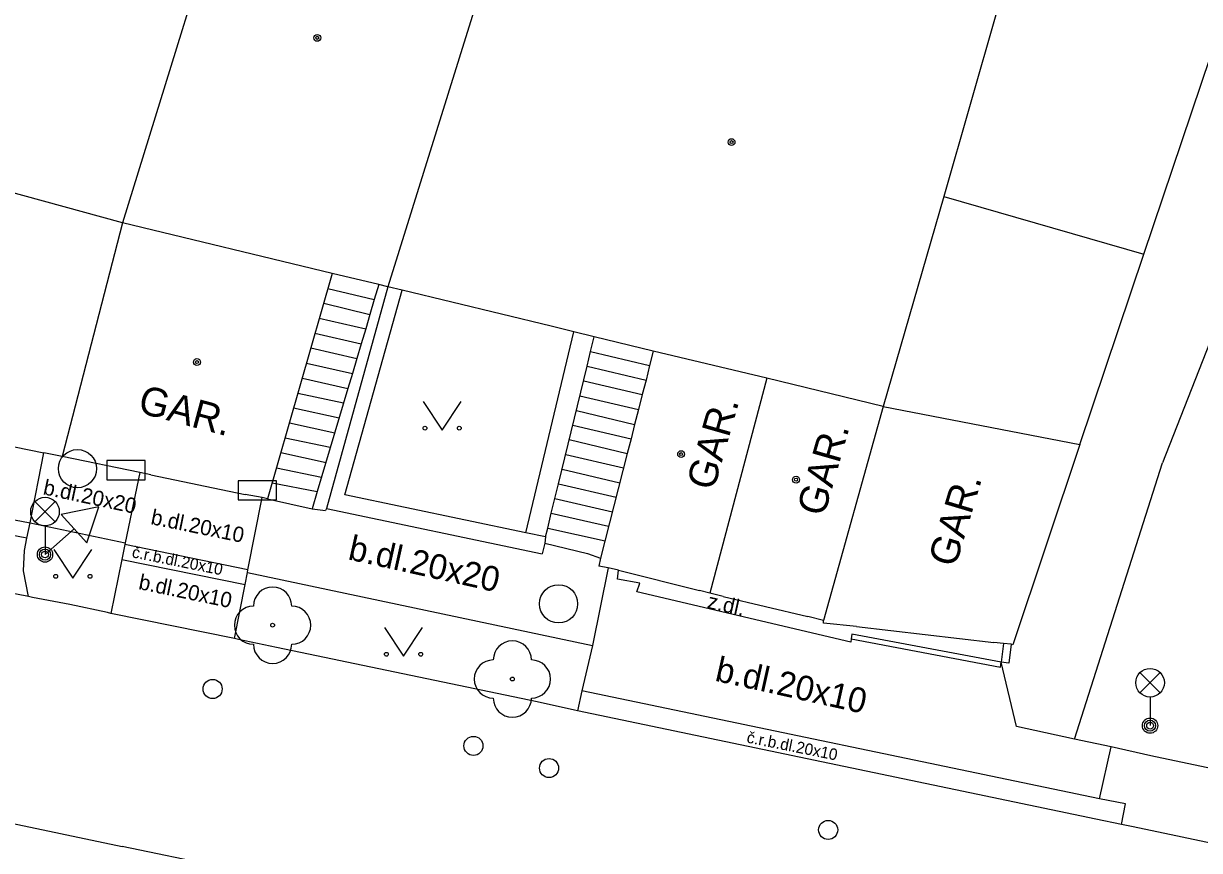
# Model space of a CAD drawing. Extents: x -595546 to -593986, y -1160845 to -1159202.
# Drawn here: x -594736.96 to -594706.17, y -1160781.24 to -1160759.59 of the extents above; entities that cross this region are included whole.
import ezdxf

# ---------------------------------------------------------------- set-up
doc = ezdxf.new("R2010")
doc.units = 0
for name, color, linetype in [('kanalizace - povrch.  znaky - skut. velikost', 7, 'Continuous'), ('Level 22', 7, 'Continuous'), ('Level 24', 7, 'Continuous'), ('Level 27', 7, 'Continuous'), ('Level 28', 7, 'Continuous'), ('Level 33', 7, 'Continuous'), ('Level 34', 7, 'Continuous'), ('Level 36', 7, 'Continuous'), ('Level 39', 7, 'Continuous'), ('Specificka linie pasportu komunikaci', 7, 'Continuous'), ('TM - budovy zdene_ betonove - VP', 7, 'Continuous'), ('TM - chodniky - VP', 7, 'Continuous'), ('TM - komunikace - VP', 7, 'Continuous'), ('TM - letecke snimky - pomocna linie', 7, 'Continuous'), ('TM - plot drateny_ kovovy - VP', 7, 'Continuous'), ('TM - podezdivka plotu - VP', 7, 'Continuous'), ('TM - pomocna konstrukcni linie', 7, 'Continuous'), ('TM - popis objektu', 7, 'Continuous'), ('TM - popis povrchu', 7, 'Continuous'), ('TM - rozhrani mezi zpev. plochami mezi sebou - VP', 7, 'Continuous'), ('TM - rozhrani ploch obecne - VP', 7, 'Continuous'), ('TM - schody - VP', 7, 'Continuous'), ('TM - vjezd na pozemek', 7, 'Continuous'), ('TM - vstup do budovy - zdene_ betonove', 7, 'Continuous'), ('TM - zed operna - VP', 7, 'Continuous')]:
    doc.layers.add(name, color=color, linetype=linetype)

msp = doc.modelspace()

# ---------------------------------------------------------------- linework, layer by layer
at = {"layer": 'kanalizace - povrch.  znaky - skut. velikost'}
for points in [[(-594715.27, -1160775.57), (-594715.29, -1160775.7)], [(-594715.29, -1160775.7), (-594711.38, -1160776.44)], [(-594711.36, -1160776.31), (-594715.27, -1160775.57)], [(-594711.38, -1160776.44), (-594711.36, -1160776.31)]]:
    msp.add_lwpolyline(points, dxfattribs=at)
at = {"layer": 'Level 22'}
for centre in [(-594730.44, -1160775.34), (-594724.16, -1160776.75)]:
    msp.add_circle(centre, 0.05, dxfattribs=at)
for centre, start, end in [((-594730.44, -1160774.84), 0, 180), ((-594730.94, -1160775.34), 90, 270), ((-594729.94, -1160775.34), 270, 90), ((-594730.44, -1160775.84), 180, 0), ((-594724.16, -1160776.25), 0, 180), ((-594724.66, -1160776.75), 90, 270), ((-594723.66, -1160776.75), 270, 90), ((-594724.16, -1160777.25), 180, 0)]:
    msp.add_arc(centre, 0.5, start, end, dxfattribs=at)
at = {"layer": 'Level 24'}
for points in [[(-594734.778, -1160771.529), (-594733.778, -1160771.529), (-594733.778, -1160771.029), (-594734.778, -1160771.029)], [(-594731.337, -1160772.058), (-594730.337, -1160772.058), (-594730.337, -1160771.558), (-594731.337, -1160771.558)]]:
    msp.add_lwpolyline(points, close=True, dxfattribs=at)
at = {"layer": 'Level 27'}
for centre in [(-594735.55, -1160771.24), (-594722.95, -1160774.78)]:
    msp.add_circle(centre, 0.5, dxfattribs=at)
at = {"layer": 'Level 28'}
for centre in [(-594732.01, -1160777.01), (-594725.18, -1160778.5), (-594723.2, -1160779.08), (-594715.89, -1160780.7)]:
    msp.add_circle(centre, 0.25, dxfattribs=at)
at = {"layer": 'Level 33'}
for p, q in [((-594736.665, -1160772.63), (-594736.135, -1160772.1)), ((-594736.665, -1160772.1), (-594736.135, -1160772.63)), ((-594736.4, -1160772.74), (-594736.4, -1160773.49)), ((-594707.725, -1160777.11), (-594707.195, -1160776.58)), ((-594707.725, -1160776.58), (-594707.195, -1160777.11)), ((-594707.46, -1160777.22), (-594707.46, -1160777.97))]:
    msp.add_line(p, q, dxfattribs=at)
for centre, radius in [((-594736.4, -1160772.365), 0.375), ((-594736.4, -1160773.49), 0.2), ((-594736.4, -1160773.49), 0.145), ((-594736.4, -1160773.49), 0.0876), ((-594707.46, -1160776.845), 0.375), ((-594707.46, -1160777.97), 0.2), ((-594707.46, -1160777.97), 0.145), ((-594707.46, -1160777.97), 0.0876)]:
    msp.add_circle(centre, radius, dxfattribs=at)
at = {"layer": 'Level 34'}
msp.add_line((-594735.64, -1160772.813), (-594736.4, -1160773.49), dxfattribs=at)
msp.add_lwpolyline([(-594735.973, -1160772.439), (-594735.307, -1160773.186), (-594734.994, -1160772.236)], close=True, dxfattribs=at)
at = {"layer": 'Level 36'}
for points in [[(-594726.5, -1160769.48), (-594726, -1160770.23), (-594725.5, -1160769.48)], [(-594736.17, -1160773.36), (-594735.67, -1160774.11), (-594735.17, -1160773.36)], [(-594727.51, -1160775.4), (-594727.01, -1160776.15), (-594726.51, -1160775.4)]]:
    msp.add_lwpolyline(points, dxfattribs=at)
for centre in [(-594726.45, -1160770.18), (-594725.551, -1160770.18), (-594736.12, -1160774.06), (-594735.221, -1160774.06), (-594727.46, -1160776.1), (-594726.561, -1160776.1)]:
    msp.add_circle(centre, 0.05, dxfattribs=at)
at = {"layer": 'Level 39'}
for centre, radius in [((-594729.27, -1160759.96), 0.09), ((-594729.27, -1160759.96), 0.0398), ((-594718.42, -1160762.69), 0.09), ((-594718.42, -1160762.69), 0.0398), ((-594732.42, -1160768.45), 0.09), ((-594732.42, -1160768.45), 0.0398), ((-594719.74, -1160770.86), 0.09), ((-594719.74, -1160770.86), 0.0398), ((-594716.73, -1160771.53), 0.09), ((-594716.73, -1160771.53), 0.0398)]:
    msp.add_circle(centre, radius, dxfattribs=at)
at = {"layer": 'Specificka linie pasportu komunikaci'}
msp.add_lwpolyline([(-594709.44, -1160778.32), (-594707.13, -1160771.09)], dxfattribs=at)
at = {"layer": 'TM - budovy zdene_ betonove - VP'}
for points in [[(-594731.13, -1160754.32), (-594734.37, -1160764.8)], [(-594724.28, -1160756.4), (-594727.42, -1160766.48)], [(-594711.48, -1160759.3), (-594712.86, -1160764.11)], [(-594734.37, -1160764.8), (-594738.52, -1160763.67)], [(-594712.86, -1160764.11), (-594714.45, -1160769.61)], [(-594734.37, -1160764.8), (-594735.95, -1160770.92)], [(-594728.88, -1160766.13), (-594734.37, -1160764.8)], [(-594728.88, -1160766.13), (-594730.57, -1160772.03)], [(-594727.66, -1160766.42), (-594728.88, -1160766.13)], [(-594727.42, -1160766.48), (-594727.66, -1160766.42)], [(-594727.05, -1160766.57), (-594727.42, -1160766.48)], [(-594723.14, -1160767.51), (-594727.05, -1160766.57)], [(-594722.55, -1160767.66), (-594723.14, -1160767.51)], [(-594722.02, -1160767.79), (-594722.55, -1160767.66)], [(-594720.47, -1160768.16), (-594722.02, -1160767.79)], [(-594720.47, -1160768.16), (-594720.57, -1160768.54), (-594720.66, -1160768.92), (-594720.76, -1160769.3), (-594720.86, -1160769.69), (-594720.96, -1160770.08), (-594721.05, -1160770.46), (-594721.15, -1160770.84), (-594721.85, -1160773.58)], [(-594717.5, -1160768.87), (-594720.47, -1160768.16)], [(-594717.5, -1160768.87), (-594718.99, -1160774.5)], [(-594714.45, -1160769.61), (-594717.5, -1160768.87)], [(-594714.45, -1160769.61), (-594716.01, -1160775.22)], [(-594714.45, -1160769.61), (-594709.3, -1160770.61)], [(-594709.3, -1160770.61), (-594711.05, -1160775.85)], [(-594735.95, -1160770.92), (-594736.43, -1160770.83)], [(-594733.92, -1160771.34), (-594735.95, -1160770.92)], [(-594733.63, -1160771.4), (-594733.92, -1160771.34)], [(-594730.71, -1160772), (-594731.16, -1160771.92)], [(-594730.57, -1160772.03), (-594730.71, -1160772)], [(-594721.85, -1160773.58), (-594721.9, -1160773.79)], [(-594721.65, -1160773.84), (-594721.9, -1160773.79)], [(-594721.38, -1160773.9), (-594721.65, -1160773.84)], [(-594718.99, -1160774.5), (-594719.26, -1160774.43)], [(-594718.64, -1160774.59), (-594718.99, -1160774.5)], [(-594716.01, -1160775.22), (-594716.42, -1160775.11)], [(-594716.01, -1160775.29), (-594716.01, -1160775.22)], [(-594715.15, -1160775.37), (-594716.01, -1160775.29)], [(-594711.3, -1160775.82), (-594711.55, -1160775.79)], [(-594711.1, -1160775.84), (-594711.3, -1160775.82)], [(-594711.05, -1160775.85), (-594711.1, -1160775.84)]]:
    msp.add_lwpolyline(points, dxfattribs=at)
at = {"layer": 'TM - chodniky - VP'}
for points in [[(-594736.88, -1160773.06), (-594736.79, -1160772.66)], [(-594736.79, -1160772.66), (-594734.3, -1160773.18)], [(-594736.94, -1160773.38), (-594736.88, -1160773.06)], [(-594736.96, -1160773.92), (-594736.94, -1160773.38)], [(-594734.31, -1160773.23), (-594734.39, -1160773.62)], [(-594734.3, -1160773.18), (-594734.31, -1160773.23)], [(-594734.39, -1160773.62), (-594734.68, -1160775.03)], [(-594736.83, -1160774.59), (-594736.96, -1160773.92)], [(-594731.16, -1160774.27), (-594731.1, -1160773.96)], [(-594731.1, -1160773.96), (-594731.09, -1160773.89)], [(-594731.1, -1160773.96), (-594722.06, -1160775.87)], [(-594731.44, -1160775.69), (-594731.16, -1160774.27)], [(-594722.06, -1160775.87), (-594722.34, -1160777.06)], [(-594710.96, -1160777.99), (-594711.36, -1160776.31)], [(-594722.34, -1160777.06), (-594722.45, -1160777.58)], [(-594709.44, -1160778.32), (-594710.96, -1160777.99)], [(-594708.48, -1160778.52), (-594709.44, -1160778.32)], [(-594707.44, -1160778.76), (-594708.48, -1160778.52)], [(-594697.12, -1160780.93), (-594707.44, -1160778.76)]]:
    msp.add_lwpolyline(points, dxfattribs=at)
at = {"layer": 'TM - komunikace - VP'}
for points in [[(-594736.83, -1160774.59), (-594742.64, -1160773.46)], [(-594736.73, -1160774.61), (-594736.83, -1160774.59)], [(-594735.75, -1160774.8), (-594736.73, -1160774.61)], [(-594734.76, -1160775.01), (-594735.75, -1160774.8)], [(-594734.68, -1160775.03), (-594734.76, -1160775.01)], [(-594731.44, -1160775.69), (-594734.68, -1160775.03)], [(-594731.33, -1160775.71), (-594731.44, -1160775.69)], [(-594730.34, -1160775.92), (-594731.33, -1160775.71)], [(-594723.51, -1160777.35), (-594730.34, -1160775.92)], [(-594722.53, -1160777.56), (-594723.51, -1160777.35)], [(-594722.45, -1160777.58), (-594722.53, -1160777.56)], [(-594708.88, -1160780.42), (-594722.45, -1160777.58)], [(-594739.23, -1160780.11), (-594734.38, -1160781.13)], [(-594708.21, -1160780.56), (-594708.88, -1160780.42)], [(-594707.9, -1160780.62), (-594708.21, -1160780.56)], [(-594697.47, -1160782.82), (-594707.9, -1160780.62)], [(-594729.33, -1160782.18), (-594734.38, -1160781.13)]]:
    msp.add_lwpolyline(points, dxfattribs=at)
at = {"layer": 'TM - letecke snimky - pomocna linie'}
for points in [[(-594707.62, -1160765.62), (-594703.12, -1160752.26)], [(-594700.06, -1160753.08), (-594707.13, -1160771.09)], [(-594712.86, -1160764.11), (-594707.62, -1160765.62)], [(-594709.3, -1160770.61), (-594707.62, -1160765.62)]]:
    msp.add_lwpolyline(points, dxfattribs=at)
at = {"layer": 'TM - plot drateny_ kovovy - VP'}
msp.add_lwpolyline([(-594722.19, -1160773.46), (-594721.85, -1160773.58)], dxfattribs=at)
at = {"layer": 'TM - podezdivka plotu - VP'}
for points in [[(-594727.66, -1160766.42), (-594727.78, -1160766.81), (-594727.89, -1160767.2), (-594728, -1160767.58), (-594728.12, -1160767.97), (-594728.23, -1160768.36), (-594728.35, -1160768.75), (-594728.47, -1160769.14), (-594729.27, -1160771.84), (-594729.4, -1160772.29)], [(-594727.42, -1160766.48), (-594729.03, -1160772.28)], [(-594729.4, -1160772.29), (-594729.05, -1160772.34)], [(-594729.03, -1160772.28), (-594729.05, -1160772.34)], [(-594729.03, -1160772.28), (-594723.38, -1160773.47)], [(-594723.29, -1160773.03), (-594723.31, -1160773.19)], [(-594723.31, -1160773.19), (-594723.38, -1160773.47)], [(-594711.3, -1160775.82), (-594711.36, -1160776.31)], [(-594711.16, -1160776.33), (-594711.36, -1160776.31)]]:
    msp.add_lwpolyline(points, dxfattribs=at)
at = {"layer": 'TM - pomocna konstrukcni linie'}
msp.add_lwpolyline([(-594723.29, -1160773.03), (-594723.23, -1160772.8), (-594723.14, -1160772.41), (-594723.05, -1160772.02), (-594722.95, -1160771.64), (-594722.2, -1160768.56), (-594722.11, -1160768.17), (-594722.02, -1160767.79)], dxfattribs=at)
at = {"layer": 'TM - rozhrani mezi zpev. plochami mezi sebou - VP'}
for points in [[(-594736.79, -1160772.66), (-594736.43, -1160770.83)], [(-594733.92, -1160771.34), (-594734.3, -1160773.18)], [(-594742.27, -1160771.61), (-594736.79, -1160772.66)], [(-594736.88, -1160773.06), (-594742.35, -1160772.01)], [(-594731.09, -1160773.89), (-594730.71, -1160772)], [(-594731.09, -1160773.89), (-594734.31, -1160773.23)], [(-594734.39, -1160773.62), (-594731.16, -1160774.27)], [(-594721.65, -1160773.84), (-594722.06, -1160775.87)], [(-594721.41, -1160774.13), (-594721.38, -1160773.9)], [(-594720.82, -1160774.24), (-594721.41, -1160774.13)], [(-594720.9, -1160774.47), (-594720.82, -1160774.24)], [(-594715.3, -1160775.78), (-594720.9, -1160774.47)], [(-594715.29, -1160775.7), (-594715.3, -1160775.78)], [(-594708.78, -1160779.89), (-594722.34, -1160777.06)], [(-594708.78, -1160779.89), (-594708.48, -1160778.52)], [(-594708.1, -1160780.02), (-594708.78, -1160779.89)], [(-594708.21, -1160780.56), (-594708.1, -1160780.02)]]:
    msp.add_lwpolyline(points, dxfattribs=at)
at = {"layer": 'TM - rozhrani ploch obecne - VP'}
msp.add_lwpolyline([(-594723.81, -1160772.92), (-594722.55, -1160767.66)], dxfattribs=at)
at = {"layer": 'TM - schody - VP'}
for points in [[(-594728.99, -1160766.52), (-594727.78, -1160766.81)], [(-594729.1, -1160766.91), (-594727.89, -1160767.2)], [(-594729.22, -1160767.3), (-594728, -1160767.58)], [(-594729.33, -1160767.69), (-594728.12, -1160767.97)], [(-594729.44, -1160768.08), (-594728.23, -1160768.36)], [(-594722.11, -1160768.17), (-594720.57, -1160768.54)], [(-594729.55, -1160768.48), (-594728.35, -1160768.75)], [(-594722.2, -1160768.56), (-594720.66, -1160768.92)], [(-594729.66, -1160768.87), (-594728.47, -1160769.14)], [(-594722.29, -1160768.94), (-594720.76, -1160769.3)], [(-594729.78, -1160769.26), (-594728.58, -1160769.52)], [(-594722.39, -1160769.33), (-594720.86, -1160769.69)], [(-594729.89, -1160769.65), (-594728.7, -1160769.91)], [(-594722.48, -1160769.72), (-594720.96, -1160770.08)], [(-594730, -1160770.04), (-594728.81, -1160770.3)], [(-594722.58, -1160770.1), (-594721.05, -1160770.46)], [(-594730.11, -1160770.43), (-594728.93, -1160770.68)], [(-594722.67, -1160770.48), (-594721.15, -1160770.84)], [(-594730.22, -1160770.82), (-594729.04, -1160771.08)], [(-594722.76, -1160770.87), (-594721.25, -1160771.22)], [(-594730.34, -1160771.22), (-594729.16, -1160771.46)], [(-594722.86, -1160771.25), (-594721.35, -1160771.61)], [(-594730.45, -1160771.61), (-594729.27, -1160771.84)], [(-594722.95, -1160771.64), (-594721.44, -1160771.99)], [(-594723.05, -1160772.02), (-594721.54, -1160772.37)], [(-594723.14, -1160772.41), (-594721.64, -1160772.75)], [(-594723.23, -1160772.8), (-594721.73, -1160773.13)]]:
    msp.add_lwpolyline(points, dxfattribs=at)
at = {"layer": 'TM - vjezd na pozemek'}
for points in [[(-594730.57, -1160772.03), (-594729.4, -1160772.29)], [(-594723.31, -1160773.19), (-594722.19, -1160773.46)]]:
    msp.add_lwpolyline(points, dxfattribs=at)
at = {"layer": 'TM - vstup do budovy - zdene_ betonove'}
for points in [[(-594738.7, -1160770.36), (-594736.43, -1160770.83)], [(-594733.63, -1160771.4), (-594731.16, -1160771.92)], [(-594721.38, -1160773.9), (-594719.26, -1160774.43)], [(-594718.64, -1160774.59), (-594716.42, -1160775.11)], [(-594715.15, -1160775.37), (-594711.55, -1160775.79)]]:
    msp.add_lwpolyline(points, dxfattribs=at)
at = {"layer": 'TM - zed operna - VP'}
for points in [[(-594728.55, -1160771.93), (-594727.05, -1160766.57)], [(-594723.81, -1160772.92), (-594728.55, -1160771.93)], [(-594723.29, -1160773.03), (-594723.81, -1160772.92)], [(-594711.1, -1160775.84), (-594711.16, -1160776.33)]]:
    msp.add_lwpolyline(points, dxfattribs=at)

# ---------------------------------------------------------------- texts
at = {"layer": 'TM - popis objektu'}
for rotation, p in [(345.02, (-594734, -1160769.76)), (74.08, (-594718.89, -1160771.84)), (74.08, (-594716, -1160772.52)), (73.3197, (-594712.56, -1160773.85))]:
    msp.add_text('GAR.', height=0.75, rotation=rotation, dxfattribs=at).set_placement(p)
at = {"layer": 'TM - popis povrchu'}
for s, height, rotation, p in [('b.dl.20x20', 0.4, 348, (-594736.47, -1160771.91)), ('b.dl.20x10', 0.4, 348.4585, (-594733.65, -1160772.69)), ('b.dl.20x20', 0.65, 347.4669, (-594728.49, -1160773.61)), ('č.r.b.dl.20x10', 0.3, 348.6559, (-594734.14, -1160773.56)), ('b.dl.20x10', 0.4, 348.2599, (-594733.97, -1160774.39)), ('z.dl.', 0.4, 347.4669, (-594719.08, -1160774.89)), ('b.dl.20x10', 0.65, 347.4669, (-594718.88, -1160776.79)), ('č.r.b.dl.20x10', 0.3, 348.6559, (-594718.04, -1160778.41))]:
    msp.add_text(s, height=height, rotation=rotation, dxfattribs=at).set_placement(p)

doc.saveas('drawing.dxf')
